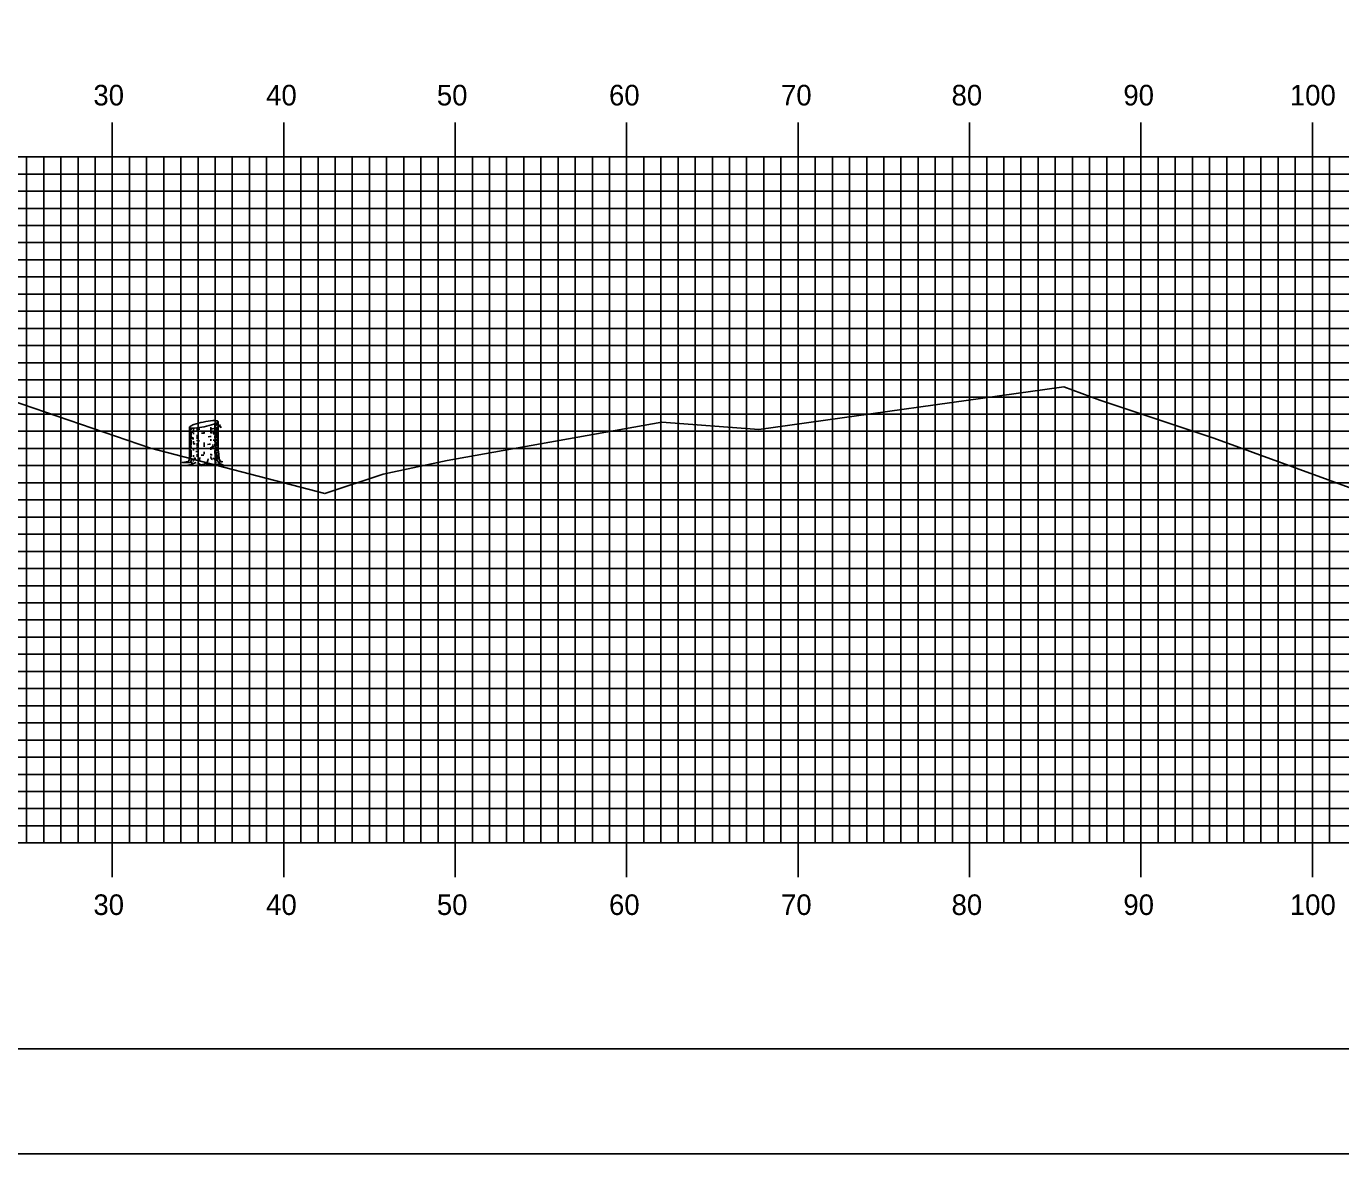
# Model space of a CAD drawing. Extents: x 860652 to 860995, y 364765 to 364985.
# Drawn here: x 860842.4 to 860919.1, y 364765.2 to 364830.9 of the extents above; entities that cross this region are included whole.
import ezdxf

# ---------------------------------------------------------------- set-up
doc = ezdxf.new("R2010")
doc.units = 0
for name, color, linetype in [('BORDER', 7, 'Continuous'), ('H_V ANNOTATION', 7, 'Continuous'), ('M_Trees_Conifer_Pay', 7, 'Continuous'), ('MAJOR', 7, 'Continuous'), ('MINOR', 7, 'Continuous'), ('PLOT BOUNDARY', 7, 'Continuous'), ('S_Roadway_Centerline', 7, 'Continuous')]:
    doc.layers.add(name, color=color, linetype=linetype)

msp = doc.modelspace()

# ---------------------------------------------------------------- linework, layer by layer
at = {"layer": 'BORDER'}
msp.add_lwpolyline([(860667.812, 364771.302), (860987.812, 364771.302), (860987.812, 364981.302), (860667.812, 364981.302)], close=True, dxfattribs=at)
at = {"layer": 'M_Trees_Conifer_Pay'}
for p, q in [((860853.506, 364807.798), (860853.506, 364807.635)), ((860853.577, 364806.223), (860853.577, 364807.87)), ((860851.913, 364805.813), (860851.913, 364807.535)), ((860851.961, 364807.497), (860851.961, 364807.026)), ((860852.019, 364807.486), (860852.019, 364807.388)), ((860852.019, 364807.314), (860852.019, 364807.11)), ((860852.019, 364807.052), (860852.019, 364806.853)), ((860852.144, 364807.478), (860852.144, 364807.246)), ((860852.144, 364807.205), (860852.144, 364807.131)), ((860852.364, 364807.499), (860852.364, 364807.331)), ((860852.364, 364807.094), (860852.364, 364806.857)), ((860852.77, 364807.267), (860852.77, 364807.172)), ((860853.16, 364807.541), (860853.16, 364807.341)), ((860853.16, 364807.283), (860853.16, 364807.195)), ((860853.388, 364807.737), (860853.388, 364807.514)), ((860853.388, 364807.425), (860853.388, 364807.378)), ((860853.388, 364807.043), (860853.388, 364806.911)), ((860853.445, 364807.242), (860853.394, 364807.182)), ((860853.506, 364807.568), (860853.506, 364807.44)), ((860853.506, 364807.253), (860853.506, 364806.917)), ((860851.961, 364806.962), (860851.961, 364806.653)), ((860851.961, 364806.606), (860851.961, 364806.114)), ((860852.019, 364806.806), (860852.019, 364806.47)), ((860852.019, 364806.417), (860852.019, 364806.281)), ((860852.144, 364806.728), (860852.144, 364806.589)), ((860852.144, 364806.318), (860852.144, 364806.176)), ((860852.364, 364806.612), (860852.364, 364806.46)), ((860852.364, 364806.417), (860852.364, 364806.243)), ((860852.77, 364806.653), (860852.77, 364806.579)), ((860852.77, 364806.554), (860852.77, 364806.406)), ((860853.16, 364806.847), (860853.16, 364806.742)), ((860853.16, 364806.375), (860853.16, 364806.229)), ((860853.388, 364806.8), (860853.388, 364806.69)), ((860853.388, 364806.554), (860853.388, 364806.413)), ((860853.506, 364806.88), (860853.506, 364806.717)), ((860853.506, 364806.67), (860853.506, 364806.453)), ((860853.506, 364806.423), (860853.506, 364806.348)), ((860853.506, 364806.308), (860853.506, 364806.134)), ((860851.961, 364806.06), (860851.961, 364805.813)), ((860852.019, 364806.182), (860852.019, 364805.803)), ((860852.144, 364805.914), (860852.144, 364805.819)), ((860852.144, 364805.42), (860852.307, 364805.484)), ((860852.364, 364805.966), (860852.364, 364805.813)), ((860852.77, 364806.114), (860852.77, 364805.961)), ((860853.16, 364805.997), (860853.16, 364805.908)), ((860853.388, 364806.186), (860853.388, 364806.013)), ((860852.581, 364805.356), (860852.455, 364805.42))]:
    msp.add_line(p, q, dxfattribs=at)
for points in [[(860853.361, 364807.331), (860853.33, 364807.246), (860853.326, 364807.178), (860853.357, 364807.115)], [(860853.394, 364807.368), (860853.431, 364807.294), (860853.478, 364807.351), (860853.536, 364807.419), (860853.629, 364807.613), (860853.693, 364807.66), (860853.724, 364807.667)], [(860853.409, 364807.115), (860853.445, 364807.242), (860853.509, 364807.358), (860853.54, 364807.425), (860853.609, 364807.571)], [(860853.623, 364807.601), (860853.699, 364807.609), (860853.771, 364807.51)], [(860852.092, 364806.84), (860852.087, 364806.936), (860852.13, 364806.913), (860852.13, 364806.818)], [(860853.232, 364806.442), (860853.244, 364806.365), (860853.291, 364806.375), (860853.279, 364806.542)], [(860853.577, 364806.223), (860853.629, 364805.961), (860853.645, 364805.688), (860853.703, 364805.562), (860853.839, 364805.531), (860853.608, 364805.494), (860853.608, 364805.494), (860853.614, 364805.447), (860853.861, 364805.352), (860853.587, 364805.369), (860853.232, 364805.389), (860852.91, 364805.379), (860852.917, 364805.461), (860852.768, 364805.379), (860852.581, 364805.356), (860852.606, 364805.288), (860852.338, 364805.331), (860852.117, 364805.304), (860851.825, 364805.321), (860852.113, 364805.379), (860852.144, 364805.42), (860851.982, 364805.478), (860851.745, 364805.488), (860851.504, 364805.488), (860851.846, 364805.546), (860851.887, 364805.626), (860851.913, 364805.813)], [(860851.961, 364805.766), (860851.94, 364805.688), (860851.92, 364805.593)], [(860852.039, 364805.745), (860852.045, 364805.63), (860851.992, 364805.541), (860851.982, 364805.478)], [(860852.202, 364805.772), (860852.202, 364805.64), (860852.113, 364805.541)], [(860852.428, 364805.531), (860852.496, 364805.626), (860852.523, 364805.766)], [(860852.917, 364805.461), (860852.991, 364805.603), (860853.001, 364805.704)], [(860853.167, 364805.83), (860853.178, 364805.704), (860853.252, 364805.661)], [(860853.445, 364805.441), (860853.431, 364805.579), (860853.357, 364805.708)], [(860853.404, 364805.935), (860853.478, 364805.83), (860853.483, 364805.657), (860853.608, 364805.494)], [(860853.503, 364806.081), (860853.509, 364805.935), (860853.556, 364805.867), (860853.567, 364805.667)]]:
    msp.add_lwpolyline(points, dxfattribs=at)
for centre, radius, start, end in [((860853.769, 364802.767), 5.179, 101.7194, 108.05939), ((860853.769, 364802.767), 5.179, 95.37941, 101.7194), ((860853.359, 364807.125), 0.802, 79.2194, 95.37941), ((860853.079, 364808.476), 0.802, 288.05939, 304.2194), ((860853.462, 364807.666), 0.251, 71.05013, 79.2194), ((860853.388, 364808.02), 0.251, 304.2194, 312.38868), ((860853.517, 364807.826), 0.0817, 56.7194, 71.05013), ((860853.502, 364807.896), 0.0817, 312.38868, 326.7194), ((860853.533, 364807.85), 0.0527, 46.92298, 56.7194), ((860853.547, 364807.866), 0.0314, 34.2194, 46.92298), ((860853.527, 364807.88), 0.0527, 326.7194, 336.51582), ((860853.551, 364807.869), 0.0264, 23.40735, 34.2194), ((860853.546, 364807.871), 0.0314, 336.51582, 349.2194), ((860853.555, 364807.87), 0.0226, 11.7194, 23.40735), ((860853.555, 364807.87), 0.0226, 0.03145, 11.7194), ((860853.551, 364807.87), 0.0264, 349.2194, 0.03145), ((860851.945, 364807.356), 0.0334, 163.94846, 180), ((860851.945, 364807.356), 0.0334, 180, 196.05154), ((860851.94, 364807.534), 0.0264, 169.2194, 180.03145), ((860851.936, 364807.534), 0.0226, 180.03145, 191.7194), ((860851.956, 364807.359), 0.0441, 196.05154, 210), ((860851.945, 364807.533), 0.0314, 156.51582, 169.2194), ((860851.936, 364807.534), 0.0226, 191.7194, 203.40735), ((860851.94, 364807.536), 0.0264, 203.40735, 214.2194), ((860851.964, 364807.525), 0.0527, 146.7194, 156.51582), ((860851.944, 364807.539), 0.0314, 214.2194, 226.92298), ((860851.972, 364807.369), 0.0624, 210, 228.74941), ((860851.989, 364807.509), 0.0817, 132.38868, 146.7194), ((860851.958, 364807.554), 0.0527, 226.92298, 236.7194), ((860851.974, 364807.579), 0.0817, 236.7194, 251.05013), ((860852.044, 364807.451), 0.172, 228.74941, 240), ((860852.102, 364807.384), 0.251, 124.2194, 132.38868), ((860852.029, 364807.738), 0.251, 251.05013, 259.2194), ((860852.243, 364807.796), 0.571, 240, 240.33672), ((860852.245, 364807.585), 0.571, 240, 247.05866), ((860852.412, 364806.929), 0.802, 108.05939, 124.2194), ((860852.132, 364808.28), 0.802, 259.2194, 275.37941), ((860852.243, 364807.796), 0.571, 246.85973, 257.98457), ((860851.722, 364812.637), 5.179, 275.37941, 281.7194), ((860852.746, 364811.547), 4.124, 264.6955, 266.73309), ((860852.744, 364811.314), 4.124, 268.07512, 270), ((860852.744, 364811.314), 4.124, 270, 270.35814), ((860851.722, 364812.637), 5.179, 281.7194, 288.05939), ((860852.745, 364811.103), 4.124, 273.70524, 275.95043), ((860852.744, 364811.314), 4.124, 275.78493, 277.05584), ((860852.746, 364811.547), 4.124, 276.23804, 278.1032), ((860853.246, 364808.029), 0.571, 278.1032, 284.36665), ((860853.246, 364808.184), 0.571, 284.43166, 292.41325), ((860853.246, 364807.585), 0.571, 284.44928, 297.04285), ((860853.246, 364808.029), 0.571, 297.0237, 300), ((860853.446, 364807.838), 0.172, 300, 311.25059), ((860853.446, 364807.684), 0.172, 300, 311.25059), ((860853.518, 364807.756), 0.0624, 311.25059, 330), ((860853.518, 364807.601), 0.0624, 311.25059, 330), ((860853.534, 364807.747), 0.0441, 330, 343.94846), ((860853.534, 364807.592), 0.0441, 330, 343.94846), ((860853.544, 364807.744), 0.0334, 343.94846, 354.21506), ((860853.544, 364807.589), 0.0334, 343.94846, 354.21506), ((860853.544, 364807.145), 0.0334, 343.94846, 354.21506), ((860851.945, 364806.91), 0.0334, 163.94846, 180), ((860851.945, 364806.91), 0.0334, 180, 196.05154), ((860851.945, 364806.7), 0.0334, 163.94846, 180), ((860851.945, 364806.7), 0.0334, 180, 196.05154), ((860851.945, 364806.463), 0.0334, 163.94846, 180), ((860851.945, 364806.463), 0.0334, 180, 196.05154), ((860851.945, 364806.265), 0.0334, 163.94846, 180), ((860851.956, 364806.913), 0.0441, 196.05154, 210), ((860851.956, 364806.703), 0.0441, 196.05154, 210), ((860851.956, 364806.466), 0.0441, 196.05154, 210), ((860851.972, 364806.922), 0.0624, 210, 228.74941), ((860851.972, 364806.712), 0.0624, 210, 228.74941), ((860851.972, 364806.475), 0.0624, 210, 228.74941), ((860852.044, 364807.004), 0.172, 228.74941, 240), ((860852.044, 364806.794), 0.172, 228.74941, 240), ((860852.044, 364806.558), 0.172, 228.74941, 240), ((860852.243, 364807.349), 0.571, 240, 240.33672), ((860852.243, 364807.139), 0.571, 240, 246.85973), ((860852.243, 364806.903), 0.571, 240, 246.85973), ((860852.243, 364807.139), 0.571, 259.27072, 261.8968), ((860852.744, 364810.657), 4.124, 261.8968, 263.14738), ((860852.744, 364810.867), 4.124, 264.08098, 266.66759), ((860852.744, 364810.42), 4.124, 264.71603, 266.31934), ((860852.744, 364810.657), 4.124, 270, 270.35814), ((860852.744, 364810.657), 4.124, 273.14934, 275.45691), ((860852.744, 364810.867), 4.124, 277.61247, 278.1032), ((860853.245, 364807.349), 0.571, 278.1032, 286.92962), ((860853.245, 364806.903), 0.571, 285.39827, 297.18959), ((860853.245, 364807.349), 0.571, 297.18959, 300), ((860853.245, 364807.139), 0.571, 297.18959, 300), ((860853.444, 364807.004), 0.172, 300, 311.25059), ((860853.444, 364806.794), 0.172, 300, 311.25059), ((860853.517, 364806.922), 0.0624, 311.25059, 330), ((860853.517, 364806.712), 0.0624, 311.25059, 330), ((860853.517, 364806.277), 0.0624, 311.25059, 330), ((860853.532, 364806.913), 0.0441, 330, 343.94846), ((860853.532, 364806.703), 0.0441, 330, 343.94846), ((860853.532, 364806.268), 0.0441, 330, 343.94846), ((860853.543, 364806.91), 0.0334, 343.94846, 354.21506), ((860853.543, 364806.7), 0.0334, 343.94846, 354.21506), ((860853.543, 364806.265), 0.0334, 343.94846, 354.21506), ((860851.945, 364806.07), 0.0334, 163.94846, 180), ((860851.945, 364806.07), 0.0334, 180, 196.05154), ((860851.945, 364805.849), 0.0334, 163.94846, 180), ((860851.945, 364805.849), 0.0334, 180, 196.05154), ((860851.956, 364806.073), 0.0441, 196.05154, 210), ((860851.956, 364805.852), 0.0441, 196.05154, 210), ((860851.972, 364806.082), 0.0624, 210, 228.74941), ((860851.972, 364805.861), 0.0624, 210, 228.74941), ((860852.044, 364806.164), 0.172, 228.74941, 240), ((860852.044, 364805.944), 0.172, 228.74941, 240), ((860852.233, 364806.711), 0.571, 241.23686, 248.02677), ((860852.243, 364806.509), 0.571, 240, 246.85973), ((860852.243, 364806.289), 0.571, 240, 244.53138), ((860852.744, 364809.807), 4.124, 262.44379, 263.51202), ((860852.744, 364810.223), 4.124, 263.49906, 265.83975), ((860852.744, 364810.027), 4.124, 267.81166, 270), ((860852.744, 364810.027), 4.124, 270, 270.13279), ((860852.744, 364810.027), 4.124, 275.78493, 276.78961), ((860852.744, 364809.807), 4.124, 277.36842, 278.1032), ((860853.245, 364806.289), 0.571, 278.1032, 281.63703), ((860853.245, 364806.509), 0.571, 288.50673, 297.27208), ((860853.245, 364806.705), 0.571, 289.29072, 300), ((860853.444, 364806.36), 0.172, 300, 311.25059), ((860853.444, 364805.944), 0.172, 300, 311.25059), ((860853.517, 364805.861), 0.0624, 311.25059, 330), ((860853.532, 364805.852), 0.0441, 330, 343.94846), ((860853.543, 364805.849), 0.0334, 343.94846, 354.21506)]:
    msp.add_arc(centre, radius, start, end, dxfattribs=at)
at = {"layer": 'MAJOR'}
for p, q in [((860847.412, 364825.306), (860847.412, 364823.302)), ((860857.412, 364825.306), (860857.412, 364823.302)), ((860867.412, 364825.306), (860867.412, 364823.302)), ((860877.412, 364825.306), (860877.412, 364823.302)), ((860887.412, 364825.306), (860887.412, 364823.302)), ((860897.412, 364825.306), (860897.412, 364823.302)), ((860907.412, 364825.306), (860907.412, 364823.302)), ((860917.412, 364825.306), (860917.412, 364823.302)), ((860677.412, 364823.302), (860957.412, 364823.302)), ((860677.412, 364823.302), (860957.412, 364823.302)), ((860847.412, 364783.302), (860847.412, 364823.302)), ((860857.412, 364783.302), (860857.412, 364823.302)), ((860867.412, 364783.302), (860867.412, 364823.302)), ((860877.412, 364783.302), (860877.412, 364823.302)), ((860887.412, 364783.302), (860887.412, 364823.302)), ((860897.412, 364783.302), (860897.412, 364823.302)), ((860907.412, 364783.302), (860907.412, 364823.302)), ((860917.412, 364783.302), (860917.412, 364823.302)), ((860677.412, 364818.302), (860957.412, 364818.302)), ((860677.412, 364813.302), (860957.412, 364813.302)), ((860677.412, 364808.302), (860957.412, 364808.302)), ((860677.412, 364803.302), (860957.412, 364803.302)), ((860677.412, 364798.302), (860957.412, 364798.302)), ((860677.412, 364793.302), (860957.412, 364793.302)), ((860677.412, 364788.302), (860957.412, 364788.302)), ((860677.412, 364783.302), (860957.412, 364783.302)), ((860677.412, 364783.302), (860957.412, 364783.302)), ((860847.412, 364781.298), (860847.412, 364783.302)), ((860857.412, 364781.298), (860857.412, 364783.302)), ((860867.412, 364781.298), (860867.412, 364783.302)), ((860877.412, 364781.298), (860877.412, 364783.302)), ((860887.412, 364781.298), (860887.412, 364783.302)), ((860897.412, 364781.298), (860897.412, 364783.302)), ((860907.412, 364781.298), (860907.412, 364783.302)), ((860917.412, 364781.298), (860917.412, 364783.302))]:
    msp.add_line(p, q, dxfattribs=at)
at = {"layer": 'MINOR'}
for p, q in [((860842.412, 364783.302), (860842.412, 364823.302)), ((860843.412, 364783.302), (860843.412, 364823.302)), ((860844.412, 364783.302), (860844.412, 364823.302)), ((860845.412, 364783.302), (860845.412, 364823.302)), ((860846.412, 364783.302), (860846.412, 364823.302)), ((860848.412, 364783.302), (860848.412, 364823.302)), ((860849.412, 364783.302), (860849.412, 364823.302)), ((860850.412, 364783.302), (860850.412, 364823.302)), ((860851.412, 364783.302), (860851.412, 364823.302)), ((860852.412, 364783.302), (860852.412, 364823.302)), ((860853.412, 364783.302), (860853.412, 364823.302)), ((860854.412, 364783.302), (860854.412, 364823.302)), ((860855.412, 364783.302), (860855.412, 364823.302)), ((860856.412, 364783.302), (860856.412, 364823.302)), ((860858.412, 364783.302), (860858.412, 364823.302)), ((860859.412, 364783.302), (860859.412, 364823.302)), ((860860.412, 364783.302), (860860.412, 364823.302)), ((860861.412, 364783.302), (860861.412, 364823.302)), ((860862.412, 364783.302), (860862.412, 364823.302)), ((860863.412, 364783.302), (860863.412, 364823.302)), ((860864.412, 364783.302), (860864.412, 364823.302)), ((860865.412, 364783.302), (860865.412, 364823.302)), ((860866.412, 364783.302), (860866.412, 364823.302)), ((860868.412, 364783.302), (860868.412, 364823.302)), ((860869.412, 364783.302), (860869.412, 364823.302)), ((860870.412, 364783.302), (860870.412, 364823.302)), ((860871.412, 364783.302), (860871.412, 364823.302)), ((860872.412, 364783.302), (860872.412, 364823.302)), ((860873.412, 364783.302), (860873.412, 364823.302)), ((860874.412, 364783.302), (860874.412, 364823.302)), ((860875.412, 364783.302), (860875.412, 364823.302)), ((860876.412, 364783.302), (860876.412, 364823.302)), ((860878.412, 364783.302), (860878.412, 364823.302)), ((860879.412, 364783.302), (860879.412, 364823.302)), ((860880.412, 364783.302), (860880.412, 364823.302)), ((860881.412, 364783.302), (860881.412, 364823.302)), ((860882.412, 364783.302), (860882.412, 364823.302)), ((860883.412, 364783.302), (860883.412, 364823.302)), ((860884.412, 364783.302), (860884.412, 364823.302)), ((860885.412, 364783.302), (860885.412, 364823.302)), ((860886.412, 364783.302), (860886.412, 364823.302)), ((860888.412, 364783.302), (860888.412, 364823.302)), ((860889.412, 364783.302), (860889.412, 364823.302)), ((860890.412, 364783.302), (860890.412, 364823.302)), ((860891.412, 364783.302), (860891.412, 364823.302)), ((860892.412, 364783.302), (860892.412, 364823.302)), ((860893.412, 364783.302), (860893.412, 364823.302)), ((860894.412, 364783.302), (860894.412, 364823.302)), ((860895.412, 364783.302), (860895.412, 364823.302)), ((860896.412, 364783.302), (860896.412, 364823.302)), ((860898.412, 364783.302), (860898.412, 364823.302)), ((860899.412, 364783.302), (860899.412, 364823.302)), ((860900.412, 364783.302), (860900.412, 364823.302)), ((860901.412, 364783.302), (860901.412, 364823.302)), ((860902.412, 364783.302), (860902.412, 364823.302)), ((860903.412, 364783.302), (860903.412, 364823.302)), ((860904.412, 364783.302), (860904.412, 364823.302)), ((860905.412, 364783.302), (860905.412, 364823.302)), ((860906.412, 364783.302), (860906.412, 364823.302)), ((860908.412, 364783.302), (860908.412, 364823.302)), ((860909.412, 364783.302), (860909.412, 364823.302)), ((860910.412, 364783.302), (860910.412, 364823.302)), ((860911.412, 364783.302), (860911.412, 364823.302)), ((860912.412, 364783.302), (860912.412, 364823.302)), ((860913.412, 364783.302), (860913.412, 364823.302)), ((860914.412, 364783.302), (860914.412, 364823.302)), ((860915.412, 364783.302), (860915.412, 364823.302)), ((860916.412, 364783.302), (860916.412, 364823.302)), ((860918.412, 364783.302), (860918.412, 364823.302)), ((860677.412, 364822.302), (860957.412, 364822.302)), ((860677.412, 364821.302), (860957.412, 364821.302)), ((860677.412, 364820.302), (860957.412, 364820.302)), ((860677.412, 364819.302), (860957.412, 364819.302)), ((860677.412, 364817.302), (860957.412, 364817.302)), ((860677.412, 364816.302), (860957.412, 364816.302)), ((860677.412, 364815.302), (860957.412, 364815.302)), ((860677.412, 364814.302), (860957.412, 364814.302)), ((860677.412, 364812.302), (860957.412, 364812.302)), ((860677.412, 364811.302), (860957.412, 364811.302)), ((860677.412, 364810.302), (860957.412, 364810.302)), ((860677.412, 364809.302), (860957.412, 364809.302)), ((860677.412, 364807.302), (860957.412, 364807.302)), ((860677.412, 364806.302), (860957.412, 364806.302)), ((860677.412, 364805.302), (860957.412, 364805.302)), ((860677.412, 364804.302), (860957.412, 364804.302)), ((860677.412, 364802.302), (860957.412, 364802.302)), ((860677.412, 364801.302), (860957.412, 364801.302)), ((860677.412, 364800.302), (860957.412, 364800.302)), ((860677.412, 364799.302), (860957.412, 364799.302)), ((860677.412, 364797.302), (860957.412, 364797.302)), ((860677.412, 364796.302), (860957.412, 364796.302)), ((860677.412, 364795.302), (860957.412, 364795.302)), ((860677.412, 364794.302), (860957.412, 364794.302)), ((860677.412, 364792.302), (860957.412, 364792.302)), ((860677.412, 364791.302), (860957.412, 364791.302)), ((860677.412, 364790.302), (860957.412, 364790.302)), ((860677.412, 364789.302), (860957.412, 364789.302)), ((860677.412, 364787.302), (860957.412, 364787.302)), ((860677.412, 364786.302), (860957.412, 364786.302)), ((860677.412, 364785.302), (860957.412, 364785.302)), ((860677.412, 364784.302), (860957.412, 364784.302))]:
    msp.add_line(p, q, dxfattribs=at)
at = {"layer": 'PLOT BOUNDARY'}
msp.add_lwpolyline([(860651.626, 364765.184), (860991.626, 364765.184), (860991.626, 364985.184), (860651.626, 364985.184)], close=True, dxfattribs=at)
at = {"layer": 'S_Roadway_Centerline'}
msp.add_lwpolyline([(860841.479, 364809.123), (860849.632, 364806.324), (860859.812, 364803.673), (860863.218, 364804.794), (860866.949, 364805.597), (860879.466, 364807.836), (860885.131, 364807.417), (860902.911, 364809.897), (860905.018, 364809.122), (860911.666, 364806.893), (860922.923, 364802.808), (860926.732, 364801.861), (860931.546, 364800.539), (860938.641, 364798.852), (860938.833, 364798.958), (860939.473, 364799.063), (860942.786, 364799.203), (860946.92, 364799.092), (860957.219, 364798.891), (860957.412, 364798.887)], dxfattribs=at)

# ---------------------------------------------------------------- texts
at = {"layer": 'H_V ANNOTATION'}
for s, p in [('30', (860846.31, 364826.302)), ('40', (860856.385, 364826.302)), ('50', (860866.342, 364826.302)), ('60', (860876.385, 364826.302)), ('70', (860886.417, 364826.302)), ('80', (860896.363, 364826.302)), ('90', (860906.385, 364826.302)), ('100', (860916.096, 364826.302)), ('30', (860846.31, 364779.102)), ('40', (860856.385, 364779.102)), ('50', (860866.342, 364779.102)), ('60', (860876.385, 364779.102)), ('70', (860886.417, 364779.102)), ('80', (860896.363, 364779.102)), ('90', (860906.385, 364779.102)), ('100', (860916.096, 364779.102))]:
    msp.add_text(s, height=1.2, dxfattribs=at).set_placement(p)

doc.saveas('drawing.dxf')
